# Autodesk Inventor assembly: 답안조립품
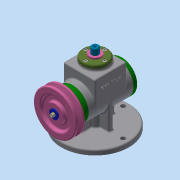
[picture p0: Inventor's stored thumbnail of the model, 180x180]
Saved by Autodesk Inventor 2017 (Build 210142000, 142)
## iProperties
Part Number: 답안조립품
Material: 일반
Document SubType Name: Assembly
Designer: 7-1
Author: 7-1
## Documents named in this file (18)
- C:\Users\7-1\Desktop\600906V1037\답안조립품.iam
- C:\Users\7-1\Desktop\600906V1037\본체.ipt
- C:\Users\7-1\Desktop\600906V1037\V-벨트풀리.ipt
- C:\Users\7-1\Desktop\600906V1037\가변스프링.ipt
- C:\Users\7-1\Desktop\600906V1037\가이드부시.ipt
- C:\Users\7-1\Desktop\600906V1037\뒤커버.ipt
- C:\Users\7-1\Desktop\600906V1037\멈춤링.ipt
- C:\Users\7-1\Desktop\600906V1037\베어링 6203.ipt
- C:\Users\7-1\Desktop\600906V1037\볼트 M4.ipt
- C:\Users\7-1\Desktop\600906V1037\상부커버.ipt
- C:\Users\7-1\Desktop\600906V1037\스프링와셔.ipt
- C:\Users\7-1\Desktop\600906V1037\스프링조립용 와셔.ipt
- C:\Users\7-1\Desktop\600906V1037\슬라이더.ipt
- C:\Users\7-1\Desktop\600906V1037\앞커버.ipt
- C:\Users\7-1\Desktop\600906V1037\오일 실 17 30 5.ipt
- C:\Users\7-1\Desktop\600906V1037\키 4x4x12.ipt
- C:\Users\7-1\Desktop\600906V1037\편심축.ipt
- C:\Users\7-1\Desktop\600906V1037\평와셔.ipt
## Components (3 placed, 3 different names)
1. V-벨트풀리:1
2. 가변스프링:1
3. 가이드부시:1
